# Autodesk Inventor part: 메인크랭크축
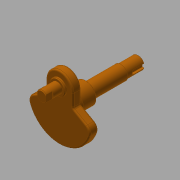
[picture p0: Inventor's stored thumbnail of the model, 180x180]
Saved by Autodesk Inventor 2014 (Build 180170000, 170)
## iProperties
Created: 2016-11
Part Number: 메인크랭크축
Material: 강철, 탄소
Document SubType Name: Modeling
Designer: mduedu
Density: 7.87 g/cm^3
Appearance: 주황색
Mass: 807.42 g
Surface Area: 206.102 cm^2
Volume: 102.595 cm^3
Author: mduedu
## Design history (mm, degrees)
sketch "스케치1" dims "d8" = 65
  geometry: L1 (-19, 26.368)-(-19, 8.368); L2 (-19, 8.368)-(-44.545, -6.381); L3 (0, 26.368)-(0, -45); L4 (19, 26.368)-(19, 8.368); L5 (19, 8.368)-(44.545, -6.381); C1 r 10 at (0, 0); C2 r 17.5 at (0, 0); A1 r 45 centre (0, 0) between (-44.545, -6.381) and (0, -45); A2 r 19 centre (0, 26.368) between (0, 45.368) and (-19, 26.368); A3 r 19 centre (0, 26.368) between (19, 26.368) and (0, 45.368); A4 r 45 centre (0, 0) between (0, -45) and (44.545, -6.381); 2 further points
  constraints: 10 end point, 8 point on circle, 6 centre point, 4 coincident, 3 symmetric about line, 2 point on line, 1 parallel, 1 tangent, 1 vertical, 1 vertical alignment, 5 other
  dimensions: "d1" = 20 diameter of C1; "d2" = 35 diameter of C2; "d4" = 18 distance of L1.start L1.end; "d5" = 120 deg angle of L2 L1; "d6" = 45 radius of A1; "d9" = 19 radius of A2
extrude "돌출1" new body sketch "스케치1" distance "d10" = 12; taper "d11" = 0 deg
extrude "돌출2" join sketch "스케치1" distance "d12" = 5; taper "d13" = 0 deg
extrude "돌출3" join sketch "스케치1" distance "d14" = 100; taper "d15" = 0 deg
sketch "스케치2"
  geometry: C1 r 7.5 at (0, 26.368); C2 r 11 at (0, 26.368); A1 r 19 centre (0, 26.368) between (19, 26.368) and (-19, 26.368) reference; 1 further point
  constraints: 2 centre point, 2 coincident
  dimensions: "d16" = 15 diameter of C1; "d17" = 22 diameter of C2
extrude "돌출4" join sketch "스케치2" distance "d18" = 3; taper "d19" = 0 deg
extrude "돌출5" join sketch "스케치2" distance "d20" = 25; taper "d21" = 0 deg
node "작업 평면1"
sketch "스케치3"
  geometry: L1 (-5.75, -4.815)-(5.75, -4.815); L2 (5.75, -4.815)-(5.75, 4.815); L3 (5.75, 4.815)-(-5.75, 4.815); L4 (-5.75, 4.815)-(-5.75, -4.815); L5 (-5.75, -4.815)-(5.75, 4.815); L6 (5.75, -4.815)-(-5.75, 4.815); A1 r 7.5 centre (0, 0) between (-5.75, 4.815) and (-5.75, -4.815); A2 r 7.5 centre (0, 0) between (5.75, -4.815) and (5.75, 4.815); 2 further points
  constraints: 12 end point, 4 point on circle, 2 centre point, 2 midpoint, 2 parallel, 1 coincident, 1 horizontal, 1 perpendicular, 2 other
  dimensions: "d23" = 11.5 distance between parallel lines of L2 L4
extrude "돌출6" cut sketch "스케치3" stored distance "d25" = 25; taper "d26" = 0 deg
fillet "모깎기1" dims "d27" = 3, "d29" = 10
fillet "모깎기2" dims "d28" = 2
sketch "스케치4"
  geometry: C1 r 15 at (0, 0); 1 further point
  constraints: 1 centre point, 1 coincident
  dimensions: "d30" = 30 diameter of C1
extrude "돌출7" join sketch "스케치4" distance "d31" = 21; taper "d32" = 0 deg
sketch "스케치5"
  geometry: C1 r 10 at (0, 0) reference; C2 r 9 at (0, 0); 1 further point
  constraints: 1 centre point
  dimensions: "d33" = 1 radial gap between concentric circles of C1 C2
extrude "돌출8" cut sketch "스케치5" distance "d34" = 25; taper "d35" = 0 deg
node "작업 평면2"
sketch "스케치6"
  geometry: L1 (-9, 0)-(9, 0) reference; L2 (-3, 0)-(3, 0); L3 (3, 0)-(3, 15); L4 (-3, 15)-(-3, 0); A1 r 3 centre (0, 15) between (3, 15) and (-3, 15); 1 further point
  constraints: 6 end point, 2 point on circle, 2 tangent, 1 centre point, 1 horizontal, 1 parallel, 1 perpendicular, 1 point on line, 1 vertical alignment
  dimensions: "d36" = 18 dimension on A1 L1; "d37" = 6 distance between parallel lines of L3 L4
extrude "돌출9" cut sketch "스케치6" distance "d38" = 3.5; taper "d39" = 0 deg
chamfer "모따기1" distance "d40" = 1; stored, may be unused: second distance "d41" = 2, angle "d42" = 45 deg
chamfer "모따기2" distance "d43" = 1; stored, may be unused: second distance "d44" = 2, angle "d45" = 45 deg
node "솔리드1"
node "투영된 루프1"
other parameters: "d3" = 38, "d22" = 13
